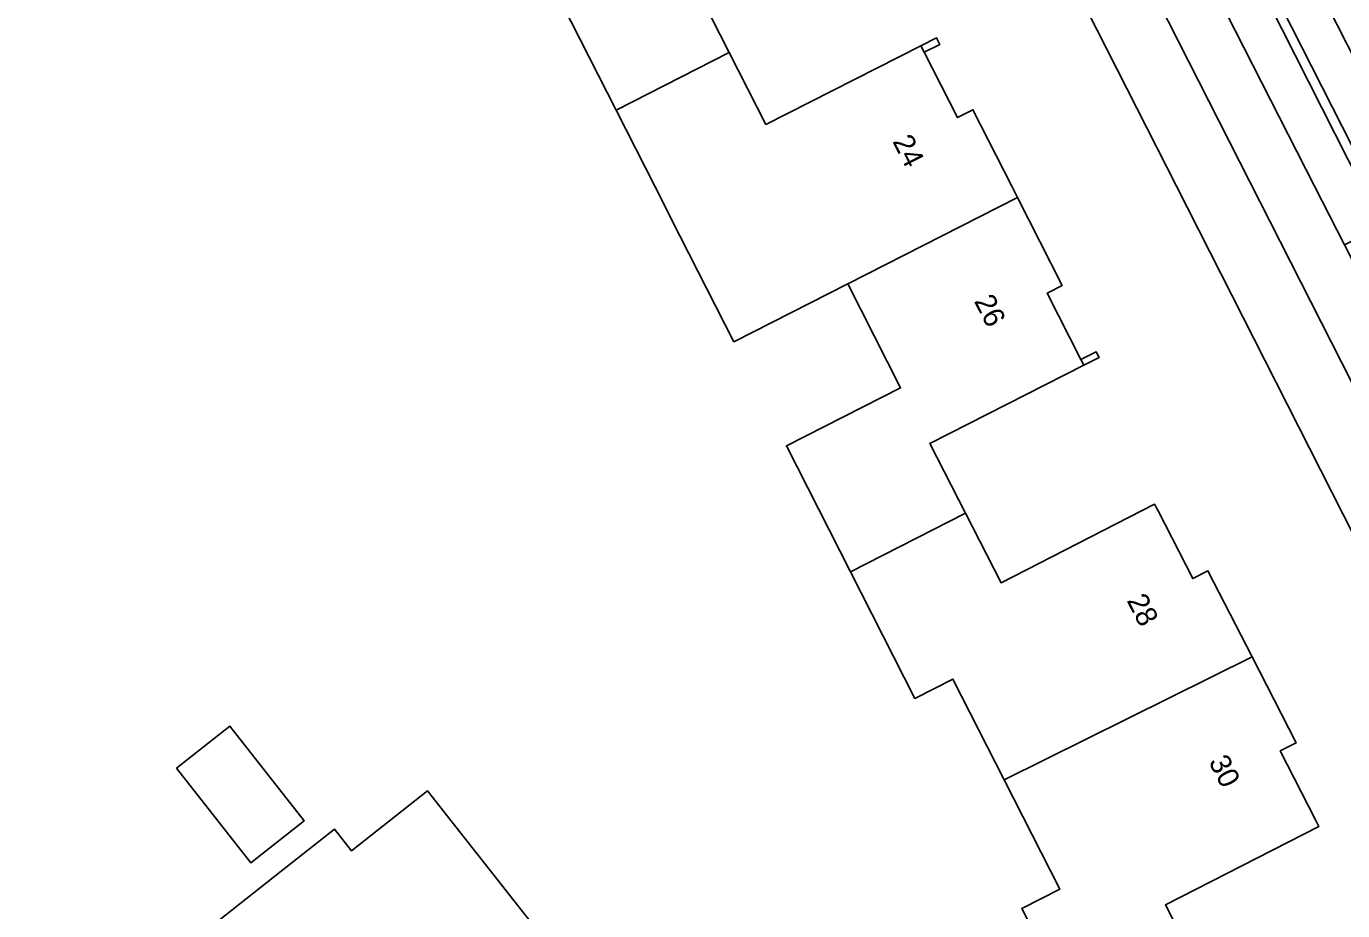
# Model space of a CAD drawing. Extents: x 162417 to 163722, y 384268 to 385417.
# Drawn here: x 163502.9 to 163565.5, y 384965.6 to 385007.6 of the extents above; entities that cross this region are included whole.
import ezdxf

# ---------------------------------------------------------------- set-up
doc = ezdxf.new("R2010")
doc.units = 0
for name, color, linetype in [('IMGEO_Berm_groen', 7, 'Continuous'), ('IMGEO_Erf', 7, 'Continuous'), ('IMGEO_Muur', 7, 'Continuous'), ('IMGEO_Pand', 7, 'Continuous'), ('IMGEO_Pand_nummerreeks', 7, 'Continuous'), ('IMGEO_Parkeervlak_open', 7, 'Continuous'), ('IMGEO_Rijbaan_lokaal_gesloten', 7, 'Continuous'), ('IMGEO_Voetpad_open', 7, 'Continuous')]:
    doc.layers.add(name, color=color, linetype=linetype)

msp = doc.modelspace()

# ---------------------------------------------------------------- linework, layer by layer
at = {"layer": 'IMGEO_Berm_groen'}
msp.add_lwpolyline([(163558.795, 385014.933), (163556.997, 385013.998), (163564.115, 385000), (163565.538, 384997.201), (163567.319, 384998.076), (163566.347, 385000)], close=True, dxfattribs=at)
at = {"layer": 'IMGEO_Erf'}
for points in [[(163571.782, 384971.962), (163557.559, 385000), (163534.443, 385045.503), (163500, 385031.078), (163425.859, 385000), (163365.371, 384974.629), (163363.507, 384973.847), (163366.161, 384967.778), (163366.55, 384967.171), (163368.242, 384964.531)], [(163553.281, 384959.628), (163550.211, 384965.663), (163552.021, 384966.584), (163549.382, 384971.771), (163546.943, 384976.566), (163545.133, 384975.645), (163542.076, 384981.664), (163539.033, 384987.654), (163544.452, 384990.409), (163541.941, 384995.347), (163536.536, 384992.599), (163533.975, 384997.635), (163532.773, 385000), (163530.938, 385003.608), (163527.927, 385009.53)], [(163534.582, 385009.76), (163536.318, 385006.346), (163538.055, 385002.93), (163545.421, 385006.676), (163546.159, 385007.051), (163546.317, 385006.738), (163545.58, 385006.363), (163547.158, 385003.259), (163547.887, 385003.629), (163549.733, 385000), (163550.012, 384999.452), (163552.135, 384995.276), (163551.416, 384994.91), (163553.021, 384991.752), (163553.746, 384992.12), (163553.883, 384991.85), (163553.158, 384991.482), (163545.85, 384987.766), (163547.54, 384984.455), (163549.23, 384981.144), (163556.522, 384984.878), (163556.686, 384984.558), (163558.334, 384981.341), (163559.054, 384981.71), (163561.148, 384977.622), (163563.242, 384973.533), (163562.49, 384973.148), (163564.17, 384969.868), (163564.327, 384969.562), (163557.032, 384965.826), (163558.766, 384962.44)]]:
    msp.add_lwpolyline(points, dxfattribs=at)
for points in [[(163510.054, 384972.323), (163512.596, 384974.322), (163516.126, 384969.834), (163513.585, 384967.835)], [(163517.384, 384950.12), (163516.948, 384949.777), (163516.672, 384950.127), (163517.108, 384950.471), (163513.88, 384954.573), (163513.444, 384954.23), (163513.166, 384954.583), (163513.602, 384954.926), (163517.23, 384957.781), (163511.929, 384964.517), (163511.333, 384964.048), (163511.104, 384964.339), (163511.7, 384964.808), (163515.034, 384967.432), (163517.566, 384969.425), (163518.37, 384968.403), (163521.985, 384971.248), (163527.844, 384963.8), (163524.188, 384961.001), (163526.689, 384957.823), (163526.874, 384957.588), (163520.878, 384952.87)]]:
    msp.add_lwpolyline(points, close=True, dxfattribs=at)
at = {"layer": 'IMGEO_Muur'}
for points in [[(163545.421, 385006.676), (163545.58, 385006.363), (163546.317, 385006.738), (163546.159, 385007.051)], [(163553.021, 384991.752), (163553.158, 384991.482), (163553.883, 384991.85), (163553.746, 384992.12)]]:
    msp.add_lwpolyline(points, close=True, dxfattribs=at)
at = {"layer": 'IMGEO_Pand'}
for points in [[(163530.746, 385017.393), (163533.344, 385012.285), (163527.927, 385009.53), (163530.938, 385003.608), (163536.318, 385006.346), (163534.582, 385009.76), (163541.97, 385013.517), (163541.834, 385013.785), (163540.202, 385016.996), (163540.927, 385017.365), (163538.825, 385021.498)], [(163532.773, 385000), (163533.975, 384997.635), (163536.536, 384992.599), (163541.941, 384995.347), (163550.012, 384999.452), (163549.733, 385000), (163547.887, 385003.629), (163547.158, 385003.259), (163545.58, 385006.363), (163545.421, 385006.676), (163538.055, 385002.93), (163536.318, 385006.346), (163530.938, 385003.608)], [(163541.941, 384995.347), (163544.452, 384990.409), (163539.033, 384987.654), (163542.076, 384981.664), (163547.54, 384984.455), (163545.85, 384987.766), (163553.158, 384991.482), (163553.021, 384991.752), (163551.416, 384994.91), (163552.135, 384995.276), (163550.012, 384999.452)], [(163545.133, 384975.645), (163546.943, 384976.566), (163549.382, 384971.771), (163561.148, 384977.622), (163559.054, 384981.71), (163558.334, 384981.341), (163556.686, 384984.558), (163556.522, 384984.878), (163549.23, 384981.144), (163547.54, 384984.455), (163542.076, 384981.664)], [(163550.211, 384965.663), (163553.281, 384959.628), (163558.766, 384962.44), (163557.032, 384965.826), (163564.327, 384969.562), (163564.17, 384969.868), (163562.49, 384973.148), (163563.242, 384973.533), (163561.148, 384977.622), (163549.382, 384971.771), (163552.021, 384966.584)], [(163510.054, 384972.323), (163513.585, 384967.835), (163516.126, 384969.834), (163512.596, 384974.322)], [(163524.188, 384961.001), (163527.844, 384963.8), (163521.985, 384971.248), (163518.37, 384968.403), (163517.566, 384969.425), (163515.034, 384967.432), (163511.7, 384964.808), (163511.929, 384964.517), (163517.23, 384957.781), (163513.602, 384954.926), (163513.88, 384954.573), (163517.108, 384950.471), (163517.384, 384950.12), (163520.878, 384952.87), (163526.874, 384957.588), (163526.689, 384957.823)]]:
    msp.add_lwpolyline(points, close=True, dxfattribs=at)
at = {"layer": 'IMGEO_Parkeervlak_open'}
for points in [[(163575.432, 384986.926), (163570.744, 384996.761), (163569.085, 385000), (163565.691, 385006.707), (163543.493, 385050.372)], [(163543.294, 385046.432), (163546.539, 385040.046), (163548.271, 385036.636), (163556.848, 385019.747), (163559.189, 385015.138), (163566.866, 385000), (163567.737, 384998.282), (163570.733, 384992.372), (163572.639, 384988.612), (163573.286, 384988.089), (163574.262, 384987.926)]]:
    msp.add_lwpolyline(points, dxfattribs=at)
at = {"layer": 'IMGEO_Rijbaan_lokaal_gesloten'}
msp.add_lwpolyline([(163572.767, 385000), (163569.995, 385005.495), (163566.848, 385011.682), (163558.831, 385027.486), (163555.713, 385033.636), (163549.154, 385046.537), (163545.346, 385054.029), (163543.493, 385050.372), (163565.691, 385006.707), (163569.085, 385000), (163570.744, 384996.761), (163575.432, 384986.926), (163576.284, 384985.149), (163579.304, 384978.533), (163579.742, 384977.454), (163582.97, 384978.933), (163581.337, 384982.561), (163578.372, 384988.883)], close=True, dxfattribs=at)
at = {"layer": 'IMGEO_Voetpad_open'}
for points in [[(163531.103, 385052.107), (163533.125, 385048.062), (163534.443, 385045.503), (163557.559, 385000), (163571.782, 384971.962), (163572.96, 384969.64), (163599.332, 384917.655), (163619.201, 384879.411), (163644.977, 384828.162), (163646.209, 384825.591), (163647.107, 384826.065), (163654.204, 384812.214), (163656.997, 384806.824), (163660.571, 384799.786), (163661.604, 384797.609), (163662.207, 384797.874), (163664.204, 384793.9), (163665.062, 384792.193), (163665.979, 384790.369)], [(163533.893, 385050.706), (163534.186, 385050.269), (163540.137, 385041.23), (163547.457, 385026.967), (163574.621, 384973.481), (163576.974, 384974.74), (163568.539, 384991.295)], [(163653.17, 384818.952), (163649.142, 384826.839), (163632.793, 384858.931), (163623.647, 384877.065), (163596.886, 384929.577), (163577.374, 384968.061), (163574.621, 384973.481), (163547.457, 385026.967), (163540.137, 385041.23), (163534.186, 385050.269), (163533.893, 385050.706)], [(163568.539, 384991.295), (163565.538, 384997.201), (163564.115, 385000), (163556.997, 385013.998), (163554.626, 385018.654), (163546.082, 385035.462), (163544.329, 385038.909), (163543.44, 385040.738)]]:
    msp.add_lwpolyline(points, dxfattribs=at)
msp.add_lwpolyline([(163558.795, 385014.933), (163566.347, 385000), (163567.319, 384998.076), (163567.737, 384998.282), (163566.866, 385000), (163559.189, 385015.138)], close=True, dxfattribs=at)

# ---------------------------------------------------------------- texts
at = {"layer": 'IMGEO_Pand_nummerreeks'}
for s, rotation, p in [('24', 296.94599, (163544.053, 385002.128)), ('26', 296.94027, (163547.928, 384994.534)), ('28', 297.12361, (163555.18, 384980.303)), ('30', 297.12361, (163559.066, 384972.637))]:
    msp.add_text(s, height=1, rotation=rotation, dxfattribs=at).set_placement(p)

doc.saveas('drawing.dxf')
